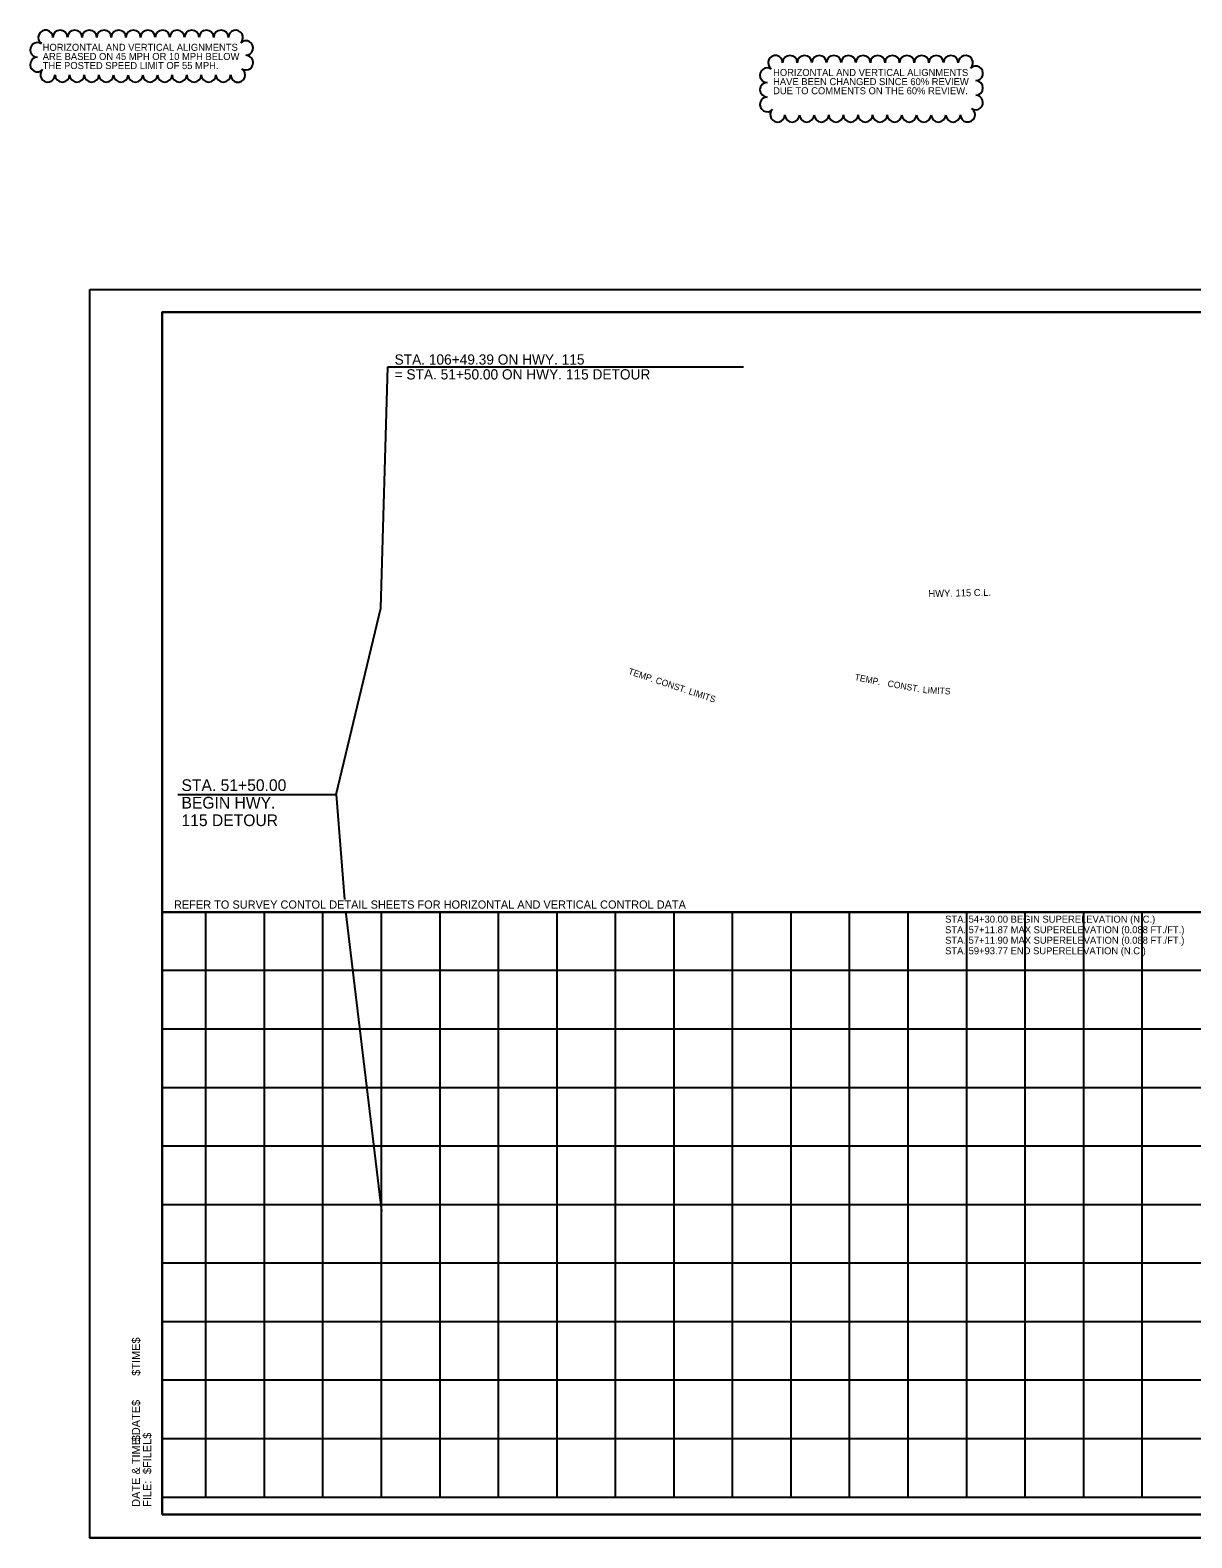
# Model space of a CAD drawing. Extents: x 9887 to 11605, y 9980 to 11268.
# Drawn here: x 9887 to 10880, y 9980 to 11268 of the extents above; entities that cross this region are included whole.
import ezdxf

# ---------------------------------------------------------------- set-up
doc = ezdxf.new("R2010")
doc.units = 0
for name, color, linetype in [('_30% NOTES', 7, 'Continuous'), ('DATE', 7, 'Continuous'), ('GREEN_TXT', 7, 'Continuous'), ('R_Alg Annot', 7, 'Continuous'), ('R_Horz Alg Curve Annot', 7, 'Continuous'), ('R_No Plot', 7, 'Continuous'), ('R_Proposed Const Limits Annot', 7, 'Continuous'), ('SEAL-INFO', 7, 'Continuous'), ('TEXT', 7, 'Continuous')]:
    doc.layers.add(name, color=color, linetype=linetype)

msp = doc.modelspace()

# ---------------------------------------------------------------- linework, layer by layer
at = {"layer": '_30% NOTES'}
for centre, start, end in [((9900.2, 11262), 0, 236.9636), ((9912.7, 11262), 0, 180), ((9925.2, 11262), 0, 180), ((9937.7, 11262), 0, 180), ((9950.2, 11262), 0, 180), ((9962.7, 11262), 0, 180), ((9975.2, 11262), 0, 180), ((9987.7, 11262), 0, 180), ((10000.2, 11262), 0, 180), ((10012.7, 11262), 0, 180), ((10025.2, 11262), 0, 180), ((10037.7, 11262), 0, 180), ((10050.2, 11262), 0, 180), ((10062.7, 11262), 314.1183, 180), ((10071.4, 11253), 270, 134.1183), ((9893.3, 11251.4), 56.9636, 270), ((10071.4, 11240.5), 237.0496, 90), ((10523.8, 11240.4), 0, 236.9636), ((10536.3, 11240.4), 0, 180), ((10548.8, 11240.4), 0, 180), ((10561.3, 11240.4), 0, 180), ((10573.8, 11240.4), 0, 180), ((10586.3, 11240.4), 0, 180), ((10598.8, 11240.4), 0, 180), ((10611.3, 11240.4), 0, 180), ((10623.8, 11240.4), 0, 180), ((10636.3, 11240.4), 0, 180), ((10648.8, 11240.4), 0, 180), ((10661.3, 11240.4), 0, 180), ((10673.8, 11240.4), 0, 180), ((10686.3, 11240.4), 314.1183, 180), ((9893.3, 11238.9), 90, 314.8317), ((9902.1, 11230.1), 134.8317, 0), ((10064.6, 11230.1), 180, 57.0496), ((10516.9, 11229.8), 56.9636, 270), ((10695, 11231.4), 270, 134.1183), ((9914.6, 11230.1), 180, 0), ((9927.1, 11230.1), 180, 0), ((9939.6, 11230.1), 180, 0), ((9952.1, 11230.1), 180, 0), ((9964.6, 11230.1), 180, 0), ((9977.1, 11230.1), 180, 0), ((9989.6, 11230.1), 180, 0), ((10002.1, 11230.1), 180, 0), ((10014.6, 11230.1), 180, 0), ((10027.1, 11230.1), 180, 0), ((10039.6, 11230.1), 180, 0), ((10052.1, 11230.1), 180, 0), ((10516.9, 11217.3), 90, 270), ((10695, 11218.9), 270, 90), ((10516.9, 11204.8), 90, 314.8317), ((10695, 11206.4), 237.0496, 90), ((10525.7, 11196), 134.8317, 0), ((10538.2, 11196), 180, 0), ((10550.7, 11196), 180, 0), ((10563.2, 11196), 180, 0), ((10575.7, 11196), 180, 0), ((10588.2, 11196), 180, 0), ((10600.7, 11196), 180, 0), ((10613.2, 11196), 180, 0), ((10625.7, 11196), 180, 0), ((10638.2, 11196), 180, 0), ((10650.7, 11196), 180, 0), ((10663.2, 11196), 180, 0), ((10675.7, 11196), 180, 0), ((10688.2, 11196), 180, 57.0496)]:
    msp.add_arc(centre, 6.25, start, end, dxfattribs=at)
at = {"layer": 'DATE'}
for p, q in [((10148.6, 10615.1), (10155.7, 10525.6)), ((10156.5, 10515.5), (10187.3, 10259.1))]:
    msp.add_line(p, q, dxfattribs=at)
msp.add_lwpolyline([(10013.2, 10615.1), (10148.6, 10615.1), (10186.7, 10774.5)], dxfattribs=at)
at = {"layer": 'GREEN_TXT'}
for p, q in [((10000, 11027.3), (11580.9, 11027.3)), ((10000, 10000), (10000, 11027.3)), ((10762.6, 11026), (10762.6, 11026)), ((10762.6, 11026), (10762.6, 11026)), ((11580.9, 10514.7), (10000, 10514.7)), ((10037.3, 10014.7), (10037.3, 10514.7)), ((10087.3, 10014.7), (10087.3, 10514.7)), ((10137.3, 10014.7), (10137.3, 10514.7)), ((10187.3, 10014.7), (10187.3, 10514.7)), ((10237.3, 10014.7), (10237.3, 10514.7)), ((10287.3, 10014.7), (10287.3, 10514.7)), ((10337.3, 10014.7), (10337.3, 10514.7)), ((10387.3, 10014.7), (10387.3, 10514.7)), ((10437.3, 10014.7), (10437.3, 10514.7)), ((10487.3, 10014.7), (10487.3, 10514.7)), ((10537.3, 10014.7), (10537.3, 10514.7)), ((10587.3, 10014.7), (10587.3, 10514.7)), ((10637.3, 10014.7), (10637.3, 10514.7)), ((10687.3, 10014.7), (10687.3, 10514.7)), ((10737.3, 10014.7), (10737.3, 10514.7)), ((10787.3, 10014.7), (10787.3, 10514.7)), ((10837.3, 10014.7), (10837.3, 10514.7)), ((11580.9, 10464.7), (10000, 10464.7)), ((11580.9, 10414.7), (10000, 10414.7)), ((11580.9, 10364.7), (10000, 10364.7)), ((11580.9, 10314.7), (10000, 10314.7)), ((11580.9, 10264.7), (10000, 10264.7)), ((11580.9, 10214.7), (10000, 10214.7)), ((11580.9, 10164.7), (10000, 10164.7)), ((11580.9, 10114.7), (10000, 10114.7)), ((11580.9, 10064.7), (10000, 10064.7)), ((11580.9, 10014.7), (10000, 10014.7)), ((10000, 10000), (10000, 10000)), ((11580.9, 10000), (10000, 10000))]:
    msp.add_line(p, q, dxfattribs=at)
at = {"layer": 'R_Alg Annot'}
msp.add_line((10192.8, 10980.5), (10496.5, 10980.5), dxfattribs=at)
msp.add_lwpolyline([(10186.7, 10774.5), (10192.8, 10980.5)], dxfattribs=at)
at = {"layer": 'R_No Plot'}
for p, q in [((9938, 11046.8), (11604.7, 11046.8)), ((9938, 9980.1), (11604.7, 9980.1))]:
    msp.add_line(p, q, dxfattribs=at)
for points in [[(9938, 11046.8), (11604.7, 11046.8), (11604.7, 9980.1), (9938, 9980.1)], [(11169.6, 11027.3), (11169.6, 10977.9), (11348.3, 10977.9), (11348.3, 10963.3), (11467.4, 10963.3), (11467.4, 10844.9), (11580.9, 10844.9), (11580.9, 10514.7), (10000, 10514.7), (10000, 11027.3)]]:
    msp.add_lwpolyline(points, close=True, dxfattribs=at)
at = {"layer": 'SEAL-INFO'}
for points in [[(10000, 10514.7), (11287.3, 10514.7), (11287.3, 10549.7), (11580.9, 10549.7), (11580.9, 10963.3), (11316.1, 10963.3), (11316.1, 10977.9), (11169.6, 10977.9), (11169.6, 11027.3), (10000, 11027.3)], [(10000, 10514.7), (11287.3, 10514.7), (11287.3, 10549.7), (11580.9, 10549.7), (11580.9, 10963.3), (11316.1, 10963.3), (11316.1, 10977.9), (11169.6, 10977.9), (11169.6, 11027.3), (10000, 11027.3)], [(10000, 10000), (11574.6, 10000), (11574.6, 10514.7), (10000, 10514.7)]]:
    msp.add_lwpolyline(points, close=True, dxfattribs=at)

# ---------------------------------------------------------------- texts
for s, p in [('$TIME$', (9981, 10118.6)), ('$DATE$', (9981, 10062.6)), ('DATE & TIME:', (9981, 10006.6)), ('$FILEL$', (9990.6, 10034.6)), ('FILE: ', (9990.6, 10006.6))]:
    msp.add_text(s, height=7, rotation=90).set_placement(p)
at = {"layer": '_30% NOTES'}
for s, p in [('ARE BASED ON 45 MPH OR 10 MPH BELOW', (9897.8, 11242.8)), ('HORIZONTAL AND VERTICAL ALIGNMENTS', (9897.8, 11250.6)), ('THE POSTED SPEED LIMIT OF 55 MPH.', (9897.8, 11235)), ('HORIZONTAL AND VERTICAL ALIGNMENTS', (10521.9, 11229.1)), ('HAVE BEEN CHANGED SINCE 60% REVIEW', (10521.9, 11221.3)), ('DUE TO COMMENTS ON THE 60% REVIEW.', (10521.9, 11213.5))]:
    msp.add_text(s, height=6, dxfattribs=at).set_placement(p)
at = {"layer": 'DATE'}
for s, p in [('STA. 51+50.00', (10016.4, 10618.2)), ('BEGIN HWY.', (10016.4, 10603.2)), ('115 DETOUR', (10016.4, 10588.2))]:
    msp.add_text(s, height=10, dxfattribs=at).set_placement(p)
at = {"layer": 'R_Alg Annot'}
for s, p in [('STA. 106+49.39 ON HWY. 115', (10198.5, 10982.5)), ('= STA. 51+50.00 ON HWY. 115 DETOUR', (10198.5, 10969.8))]:
    msp.add_text(s, height=8.75, dxfattribs=at).set_placement(p)
at = {"layer": 'R_Horz Alg Curve Annot'}
for s, p in [('STA. 54+30.00 BEGIN SUPERELEVATION (N.C.)', (10668.9, 10505.7)), ('STA. 57+11.87 MAX SUPERELEVATION (0.088 FT./FT.)', (10668.9, 10496.7)), ('STA. 57+11.90 MAX SUPERELEVATION (0.088 FT./FT.)', (10668.9, 10487.7)), ('STA. 59+93.77 END SUPERELEVATION (N.C.)', (10668.9, 10478.7))]:
    msp.add_text(s, height=6, dxfattribs=at).set_placement(p)
at = {"layer": 'R_Proposed Const Limits Annot'}
for s, rotation, p in [('TEMP. CONST. LIMITS', 341.6298, (10397.7, 10718.2)), ('TEMP. ', 348.1706, (10591.2, 10713.1)), ('CONST. ', 349.7925, (10619.4, 10707.5)), (' LIMITS', 357.0022, (10647.7, 10702))]:
    msp.add_text(s, height=5.5, rotation=rotation, dxfattribs=at).set_placement(p)
at = {"layer": 'TEXT'}
msp.add_text('HWY. 115 C.L.', height=6, rotation=1.3073, dxfattribs=at).set_placement((10654.7, 10783.8))
msp.add_text('REFER TO SURVEY CONTOL DETAIL SHEETS FOR HORIZONTAL AND VERTICAL CONTROL DATA', height=7, dxfattribs=at).set_placement((10010, 10517.7))

doc.saveas('drawing.dxf')
